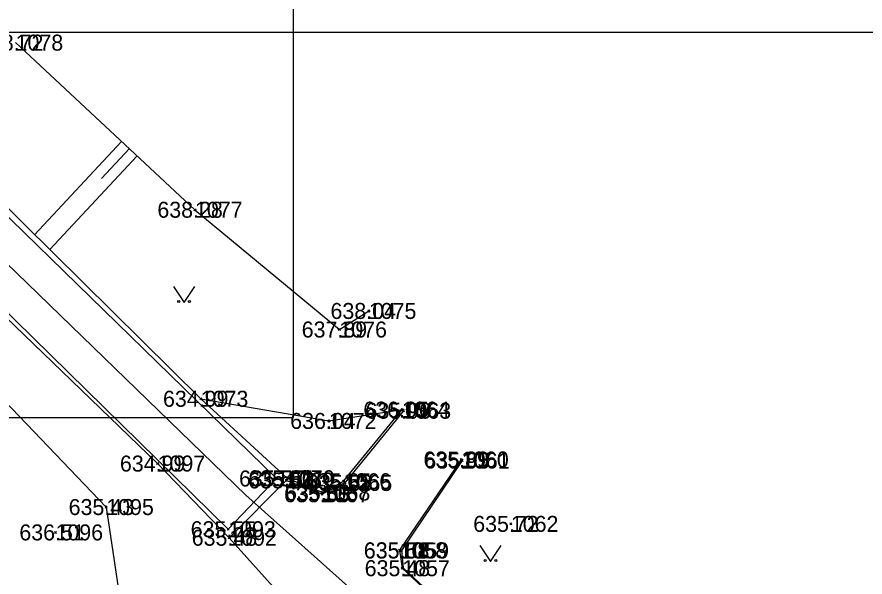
# Model space of a CAD drawing. Extents: x -844765 to -843273, y -997542 to -995529.
# Drawn here: x -844024.32 to -843984.55, y -996945.26 to -996918.98 of the extents above; entities that cross this region are included whole.
import ezdxf

# ---------------------------------------------------------------- set-up
doc = ezdxf.new("R2010")
doc.units = 0
for name, color, linetype in [('Benešův rám', 7, 'Continuous'), ('Betonový strop', 7, 'Continuous'), ('Dno', 7, 'Continuous'), ('Osa', 7, 'Continuous'), ('Přítoky', 7, 'Continuous'), ('Sítě podzemní nerozlišené', 7, 'Continuous'), ('Vrstva 63', 7, 'Continuous'), ('Číslo bodu', 7, 'Continuous'), ('Řezy', 7, 'Continuous')]:
    doc.layers.add(name, color=color, linetype=linetype)

msp = doc.modelspace()

# ---------------------------------------------------------------- linework, layer by layer
at = {"layer": 'Benešův rám'}
for p, q in [((-844012.14, -996940.64), (-844042.08, -996911.45)), ((-844044.28, -996913.72), (-844014.41, -996943.02)), ((-844014.41, -996943.02), (-844012.14, -996940.64))]:
    msp.add_line(p, q, dxfattribs=at)
msp.add_lwpolyline([(-844041.85, -996911.26), (-844029.58, -996923.18), (-844015.7, -996936.9), (-844011.65, -996940.63), (-844011.69, -996940.73), (-844014.36, -996943.42), (-844017.72, -996939.94), (-844028.46, -996929.58), (-844044.49, -996913.84)], dxfattribs=at)
at = {"layer": 'Betonový strop'}
for p, q in [((-844030.01, -996931.68), (-844020.13, -996941.98)), ((-844009, -996940.77), (-844006.26, -996937.41)), ((-844006.19, -996937.46), (-844008.95, -996940.85)), ((-844011.65, -996940.63), (-844009.98, -996941.3)), ((-844010.01, -996941.38), (-844011.69, -996940.73)), ((-844008.95, -996940.85), (-844010.01, -996941.38)), ((-844009.98, -996941.3), (-844009, -996940.77)), ((-844020.13, -996941.98), (-844019.51, -996946.17)), ((-844014.36, -996943.42), (-844006.97, -996951.66))]:
    msp.add_line(p, q, dxfattribs=at)
for points in [[(-844003.49, -996939.75), (-844006.38, -996944.01), (-844006.25, -996944.85), (-844002.87, -996948)], [(-844003.45, -996939.8), (-844006.29, -996944.02), (-844006.204, -996944.839), (-844002.844, -996947.97)]]:
    msp.add_lwpolyline(points, dxfattribs=at)
at = {"layer": 'Dno'}
for points in [[(-844016.981, -996931.638), (-844016.481, -996932.388), (-844015.981, -996931.638)], [(-844002.613, -996943.791), (-844002.113, -996944.541), (-844001.613, -996943.791)]]:
    msp.add_lwpolyline(points, dxfattribs=at)
for centre in [(-844016.731, -996932.338), (-844016.231, -996932.338), (-844002.363, -996944.491), (-844001.863, -996944.491)]:
    msp.add_circle(centre, 0.05, dxfattribs=at)
at = {"layer": 'Osa'}
for p, q in [((-844024.38, -996920.19), (-844015.97, -996928.03)), ((-844015.97, -996928.03), (-844009.2, -996933.65)), ((-844009.2, -996933.65), (-844007.82, -996932.78)), ((-844015.7, -996936.9), (-844009.69, -996937.94)), ((-844009.69, -996937.94), (-844006.26, -996937.41))]:
    msp.add_line(p, q, dxfattribs=at)
msp.add_lwpolyline([(-843905.21, -997017.86), (-843921.14, -997005.98), (-843938.96, -996993.88), (-843947.495, -996988.618), (-843954.56, -996984.215), (-843962.927, -996978.74), (-843971.295, -996973.265), (-843979.6, -996967.703), (-843987.905, -996962.14), (-843995.94, -996956.078), (-844003.975, -996950.015), (-844013.59, -996941.43), (-844025.885, -996929.505), (-844043.745, -996912.055), (-844059.135, -996894.103)], dxfattribs=at)
at = {"layer": 'Přítoky'}
for p, q in [((-844019.41, -996924.823), (-844023.49, -996929.2)), ((-844019.044, -996925.164), (-844020.353, -996926.568)), ((-844018.678, -996925.505), (-844022.778, -996929.903))]:
    msp.add_line(p, q, dxfattribs=at)
at = {"layer": 'Sítě podzemní nerozlišené'}
for p, q in [((-844015.97, -996928.03), (-844016.02, -996927.98)), ((-844015.97, -996928.03), (-844016.02, -996928.08)), ((-844015.97, -996928.03), (-844015.92, -996927.98)), ((-844015.97, -996928.03), (-844015.92, -996928.08)), ((-844007.82, -996932.78), (-844007.87, -996932.73)), ((-844007.82, -996932.78), (-844007.77, -996932.73)), ((-844007.82, -996932.78), (-844007.87, -996932.83)), ((-844007.82, -996932.78), (-844007.77, -996932.83)), ((-844009.2, -996933.65), (-844009.25, -996933.6)), ((-844009.2, -996933.65), (-844009.25, -996933.7)), ((-844009.2, -996933.65), (-844009.15, -996933.6)), ((-844009.2, -996933.65), (-844009.15, -996933.7)), ((-844015.7, -996936.9), (-844015.75, -996936.85)), ((-844015.7, -996936.9), (-844015.75, -996936.95)), ((-844015.7, -996936.9), (-844015.65, -996936.85)), ((-844015.7, -996936.9), (-844015.65, -996936.95)), ((-844006.26, -996937.41), (-844006.31, -996937.36)), ((-844006.26, -996937.41), (-844006.31, -996937.46)), ((-844006.26, -996937.41), (-844006.21, -996937.36)), ((-844006.26, -996937.41), (-844006.21, -996937.46)), ((-844006.19, -996937.46), (-844006.24, -996937.41)), ((-844006.19, -996937.46), (-844006.24, -996937.51)), ((-844006.19, -996937.46), (-844006.14, -996937.41)), ((-844006.19, -996937.46), (-844006.14, -996937.51)), ((-844009.69, -996937.94), (-844009.74, -996937.89)), ((-844009.69, -996937.94), (-844009.64, -996937.89)), ((-844009.69, -996937.94), (-844009.74, -996937.99)), ((-844009.69, -996937.94), (-844009.64, -996937.99)), ((-844017.72, -996939.94), (-844017.77, -996939.89)), ((-844017.72, -996939.94), (-844017.67, -996939.89)), ((-844003.49, -996939.75), (-844003.54, -996939.7)), ((-844003.49, -996939.75), (-844003.54, -996939.8)), ((-844003.45, -996939.8), (-844003.5, -996939.75)), ((-844003.45, -996939.8), (-844003.5, -996939.85)), ((-844003.49, -996939.75), (-844003.44, -996939.7)), ((-844003.49, -996939.75), (-844003.44, -996939.8)), ((-844003.45, -996939.8), (-844003.4, -996939.75)), ((-844003.45, -996939.8), (-844003.4, -996939.85)), ((-844017.72, -996939.94), (-844017.77, -996939.99)), ((-844017.72, -996939.94), (-844017.67, -996939.99)), ((-844012.14, -996940.64), (-844012.19, -996940.59)), ((-844012.14, -996940.64), (-844012.19, -996940.69)), ((-844012.14, -996940.64), (-844012.09, -996940.59)), ((-844012.14, -996940.64), (-844012.09, -996940.69)), ((-844011.69, -996940.73), (-844011.74, -996940.68)), ((-844011.65, -996940.63), (-844011.7, -996940.58)), ((-844011.65, -996940.63), (-844011.7, -996940.68)), ((-844011.69, -996940.73), (-844011.64, -996940.68)), ((-844011.65, -996940.63), (-844011.6, -996940.58)), ((-844011.65, -996940.63), (-844011.6, -996940.68)), ((-844011.69, -996940.73), (-844011.74, -996940.78)), ((-844011.69, -996940.73), (-844011.64, -996940.78)), ((-844009, -996940.77), (-844009.05, -996940.72)), ((-844009, -996940.77), (-844009.05, -996940.82)), ((-844009, -996940.77), (-844008.95, -996940.72)), ((-844009, -996940.77), (-844008.95, -996940.82)), ((-844008.95, -996940.85), (-844009, -996940.8)), ((-844008.95, -996940.85), (-844009, -996940.9)), ((-844008.95, -996940.85), (-844008.9, -996940.8)), ((-844008.95, -996940.85), (-844008.9, -996940.9)), ((-844010.01, -996941.38), (-844010.06, -996941.33)), ((-844010.01, -996941.38), (-844010.06, -996941.43)), ((-844009.98, -996941.3), (-844010.03, -996941.25)), ((-844009.98, -996941.3), (-844010.03, -996941.35)), ((-844010.01, -996941.38), (-844009.96, -996941.33)), ((-844010.01, -996941.38), (-844009.96, -996941.43)), ((-844009.98, -996941.3), (-844009.93, -996941.25)), ((-844009.98, -996941.3), (-844009.93, -996941.35)), ((-844020.13, -996941.98), (-844020.18, -996941.93)), ((-844020.13, -996941.98), (-844020.18, -996942.03)), ((-844020.13, -996941.98), (-844020.08, -996941.93)), ((-844020.13, -996941.98), (-844020.08, -996942.03)), ((-844014.41, -996943.02), (-844014.46, -996942.97)), ((-844014.41, -996943.02), (-844014.46, -996943.07)), ((-844014.41, -996943.02), (-844014.36, -996942.97)), ((-844014.41, -996943.02), (-844014.36, -996943.07)), ((-844001.16, -996942.77), (-844001.21, -996942.72)), ((-844001.16, -996942.77), (-844001.21, -996942.82)), ((-844001.16, -996942.77), (-844001.11, -996942.72)), ((-844001.16, -996942.77), (-844001.11, -996942.82)), ((-844022.51, -996943.17), (-844022.56, -996943.12)), ((-844022.51, -996943.17), (-844022.56, -996943.22)), ((-844022.51, -996943.17), (-844022.46, -996943.12)), ((-844022.51, -996943.17), (-844022.46, -996943.22)), ((-844014.36, -996943.42), (-844014.41, -996943.37)), ((-844014.36, -996943.42), (-844014.41, -996943.47)), ((-844014.36, -996943.42), (-844014.31, -996943.37)), ((-844014.36, -996943.42), (-844014.31, -996943.47)), ((-844006.38, -996944.01), (-844006.43, -996943.96)), ((-844006.38, -996944.01), (-844006.43, -996944.06)), ((-844006.38, -996944.01), (-844006.33, -996943.96)), ((-844006.38, -996944.01), (-844006.33, -996944.06)), ((-844006.29, -996944.02), (-844006.34, -996943.97)), ((-844006.29, -996944.02), (-844006.34, -996944.07)), ((-844006.29, -996944.02), (-844006.24, -996943.97)), ((-844006.29, -996944.02), (-844006.24, -996944.07)), ((-844006.25, -996944.85), (-844006.3, -996944.8)), ((-844006.25, -996944.85), (-844006.3, -996944.9)), ((-844006.25, -996944.85), (-844006.2, -996944.8)), ((-844006.25, -996944.85), (-844006.2, -996944.9))]:
    msp.add_line(p, q, dxfattribs=at)
at = {"layer": 'Vrstva 63'}
for points in [[(-844201.344, -996937.781), (-844011.344, -996937.781), (-844011.344, -996795.281), (-844201.344, -996795.281)], [(-844050.304, -997062.218), (-843860.304, -997062.218), (-843860.304, -996919.718), (-844050.304, -996919.718)]]:
    msp.add_lwpolyline(points, close=True, dxfattribs=at)

# ---------------------------------------------------------------- texts
at = {"layer": 'Číslo bodu'}
for s, p in [('1078', (-844024.38, -996920.565)), ('1077', (-844015.97, -996928.405)), ('1075', (-844007.82, -996933.155)), ('1076', (-844009.2, -996934.025)), ('1073', (-844015.7, -996937.275)), ('1064', (-844006.26, -996937.785)), ('1063', (-844006.19, -996937.835)), ('1072', (-844009.69, -996938.315)), ('1060', (-844003.49, -996940.125)), ('1061', (-844003.45, -996940.175)), ('1097', (-844017.72, -996940.315)), ('1071', (-844012.14, -996941.015)), ('1070', (-844011.65, -996941.005)), ('1069', (-844011.69, -996941.105)), ('1066', (-844009, -996941.145)), ('1065', (-844008.95, -996941.225)), ('1067', (-844010.01, -996941.755)), ('1068', (-844009.98, -996941.675)), ('1095', (-844020.13, -996942.355)), ('1093', (-844014.41, -996943.395)), ('1062', (-844001.16, -996943.145)), ('1096', (-844022.51, -996943.545)), ('1092', (-844014.36, -996943.795)), ('1058', (-844006.38, -996944.385)), ('1059', (-844006.29, -996944.395)), ('1057', (-844006.25, -996945.225))]:
    msp.add_text(s, height=0.75, dxfattribs=at).set_placement(p)
at = {"layer": 'Řezy'}
for s, p in [('638.72', (-844026.143, -996920.565)), ('638.28', (-844017.733, -996928.405)), ('638.04', (-844009.615, -996933.155)), ('637.89', (-844010.966, -996934.025)), ('634.99', (-844017.469, -996937.275)), ('636.05', (-844008.076, -996937.785)), ('635.96', (-844007.976, -996937.835)), ('636.04', (-844011.506, -996938.315)), ('635.89', (-844005.256, -996940.125)), ('635.95', (-844005.216, -996940.175)), ('634.99', (-844019.489, -996940.315)), ('635.57', (-844013.903, -996941.015)), ('635.60', (-844013.466, -996941.005)), ('635.56', (-844013.473, -996941.105)), ('635.65', (-844010.783, -996941.145)), ('635.58', (-844010.713, -996941.225)), ('635.56', (-844011.793, -996941.755)), ('635.59', (-844011.746, -996941.675)), ('635.43', (-844021.893, -996942.355)), ('635.55', (-844016.173, -996943.395)), ('635.72', (-844002.923, -996943.145)), ('636.51', (-844024.205, -996943.545)), ('635.48', (-844016.123, -996943.795)), ('635.51', (-844008.054, -996944.385)), ('635.58', (-844008.053, -996944.395)), ('635.48', (-844008.013, -996945.225))]:
    msp.add_text(s, height=0.75, dxfattribs=at).set_placement(p)

doc.saveas('drawing.dxf')
